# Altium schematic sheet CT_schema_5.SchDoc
size 263 x 177 mm
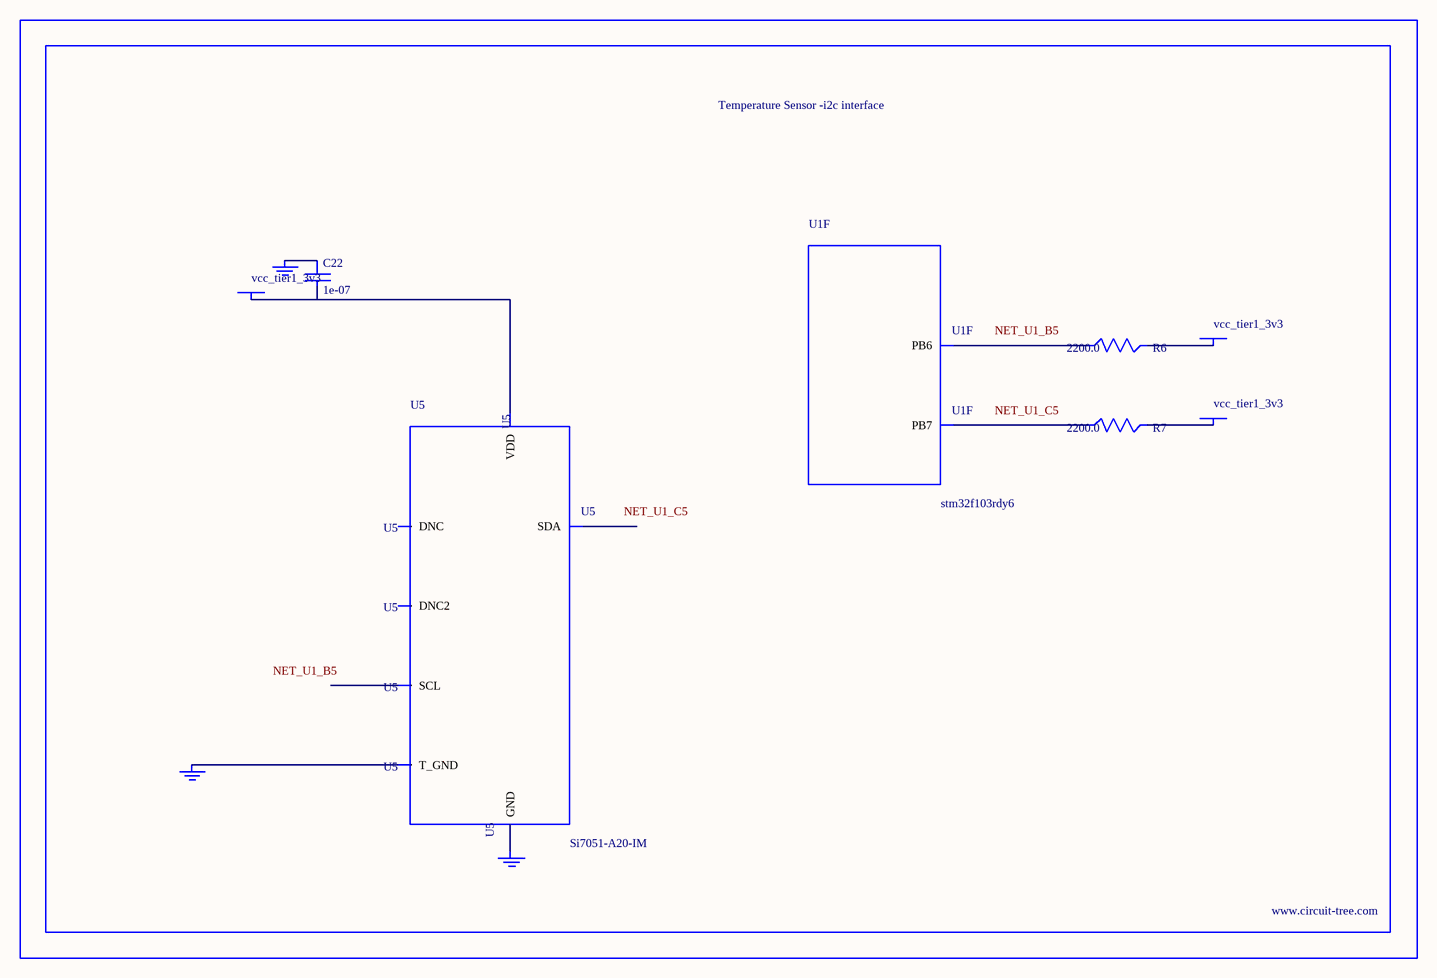
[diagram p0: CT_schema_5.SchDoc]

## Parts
BORDER4  (no value)
C22  1e-07  [C0402]
GND_INSTANCE_4_0  (no value)
GND_INSTANCE_4_1  (no value)
GND_INSTANCE_4_2  (no value)
POWER_INSTANCE_4_0  vcc_tier1_3v3
POWER_INSTANCE_4_1  vcc_tier1_3v3
POWER_INSTANCE_4_2  vcc_tier1_3v3
R6  2200.0  [R0603]
R7  2200.0  [R0603]
U1  stm32f103rdy6  [WLCSP64]  (part F of 7)
U5  Si7051-A20-IM  [DFN-6]

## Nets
NetC22_1: C22.1 GND_INSTANCE_4_0.0(GND)
NetC22_2: C22.2 POWER_INSTANCE_4_0.0(PWR) U5.5(VDD)
NetGND_INSTANCE_4_1_0: GND_INSTANCE_4_1.0(GND) U5.7(T_GND)
NetGND_INSTANCE_4_2_0: GND_INSTANCE_4_2.0(GND) U5.2(GND)
NetPOWER_INSTANCE_4_1_0: POWER_INSTANCE_4_1.0(PWR) R6.2
NetPOWER_INSTANCE_4_2_0: POWER_INSTANCE_4_2.0(PWR) R7.2
NetR6_1: R6.1 U1.B5(PB6)
NetR7_1: R7.1 U1.C5(PB7)

Not connected (* = marked no-connect by the designer): U5 1(SDA) 3(DNC) 4(DNC2) 6(SCL)

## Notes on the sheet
- Labels drawn without touching a wire or pin: NET_U1_B5, NET_U1_C5

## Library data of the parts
BORDER4 = BORDER_PAGE4
C22 = C0402C104K3RACTU
GND_INSTANCE_4_0-GND_INSTANCE_4_2 = GND
POWER_INSTANCE_4_0-POWER_INSTANCE_4_2 = PWR
R6 R7 = RC0603JR-072K2L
